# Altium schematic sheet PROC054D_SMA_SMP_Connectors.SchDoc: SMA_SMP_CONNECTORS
size 558 x 431 mm; Date: Not shown in title block; ApprovedBy: Not shown in title block; CheckedBy: Not shown in title block; Author: Not shown in title block; CompanyName: Not shown in title block; DrawnBy: a0271760; Engineer: Not shown in title block; Organization: Not shown in title block; Address1: Not shown in title block; Address2: Not shown in title block; Address3: Not shown in title block; Address4: Not shown in title block; DocumentNumber: 15; Revision: Use project pAWRameter SCH_Rev; SheetNumber: 15; SheetTotal: 19; PageSetup: Record=PageOptions¦CenterHorizontal=True¦CenterVertical=True¦PrintScale=1.00¦XCorrection=1.00¦YCorrection=1.00¦PrintKind=0¦BorderSize=5000000¦LeftOffset=0¦BottomOffset=0¦Orientation=2¦PaperLength=1000¦PaperWidth=1000¦Scale=100¦PaperSource=15¦PrintQuality=600¦MediaType=1¦DitherType=10¦PaperKind=Letter¦PrintScaleMode=1
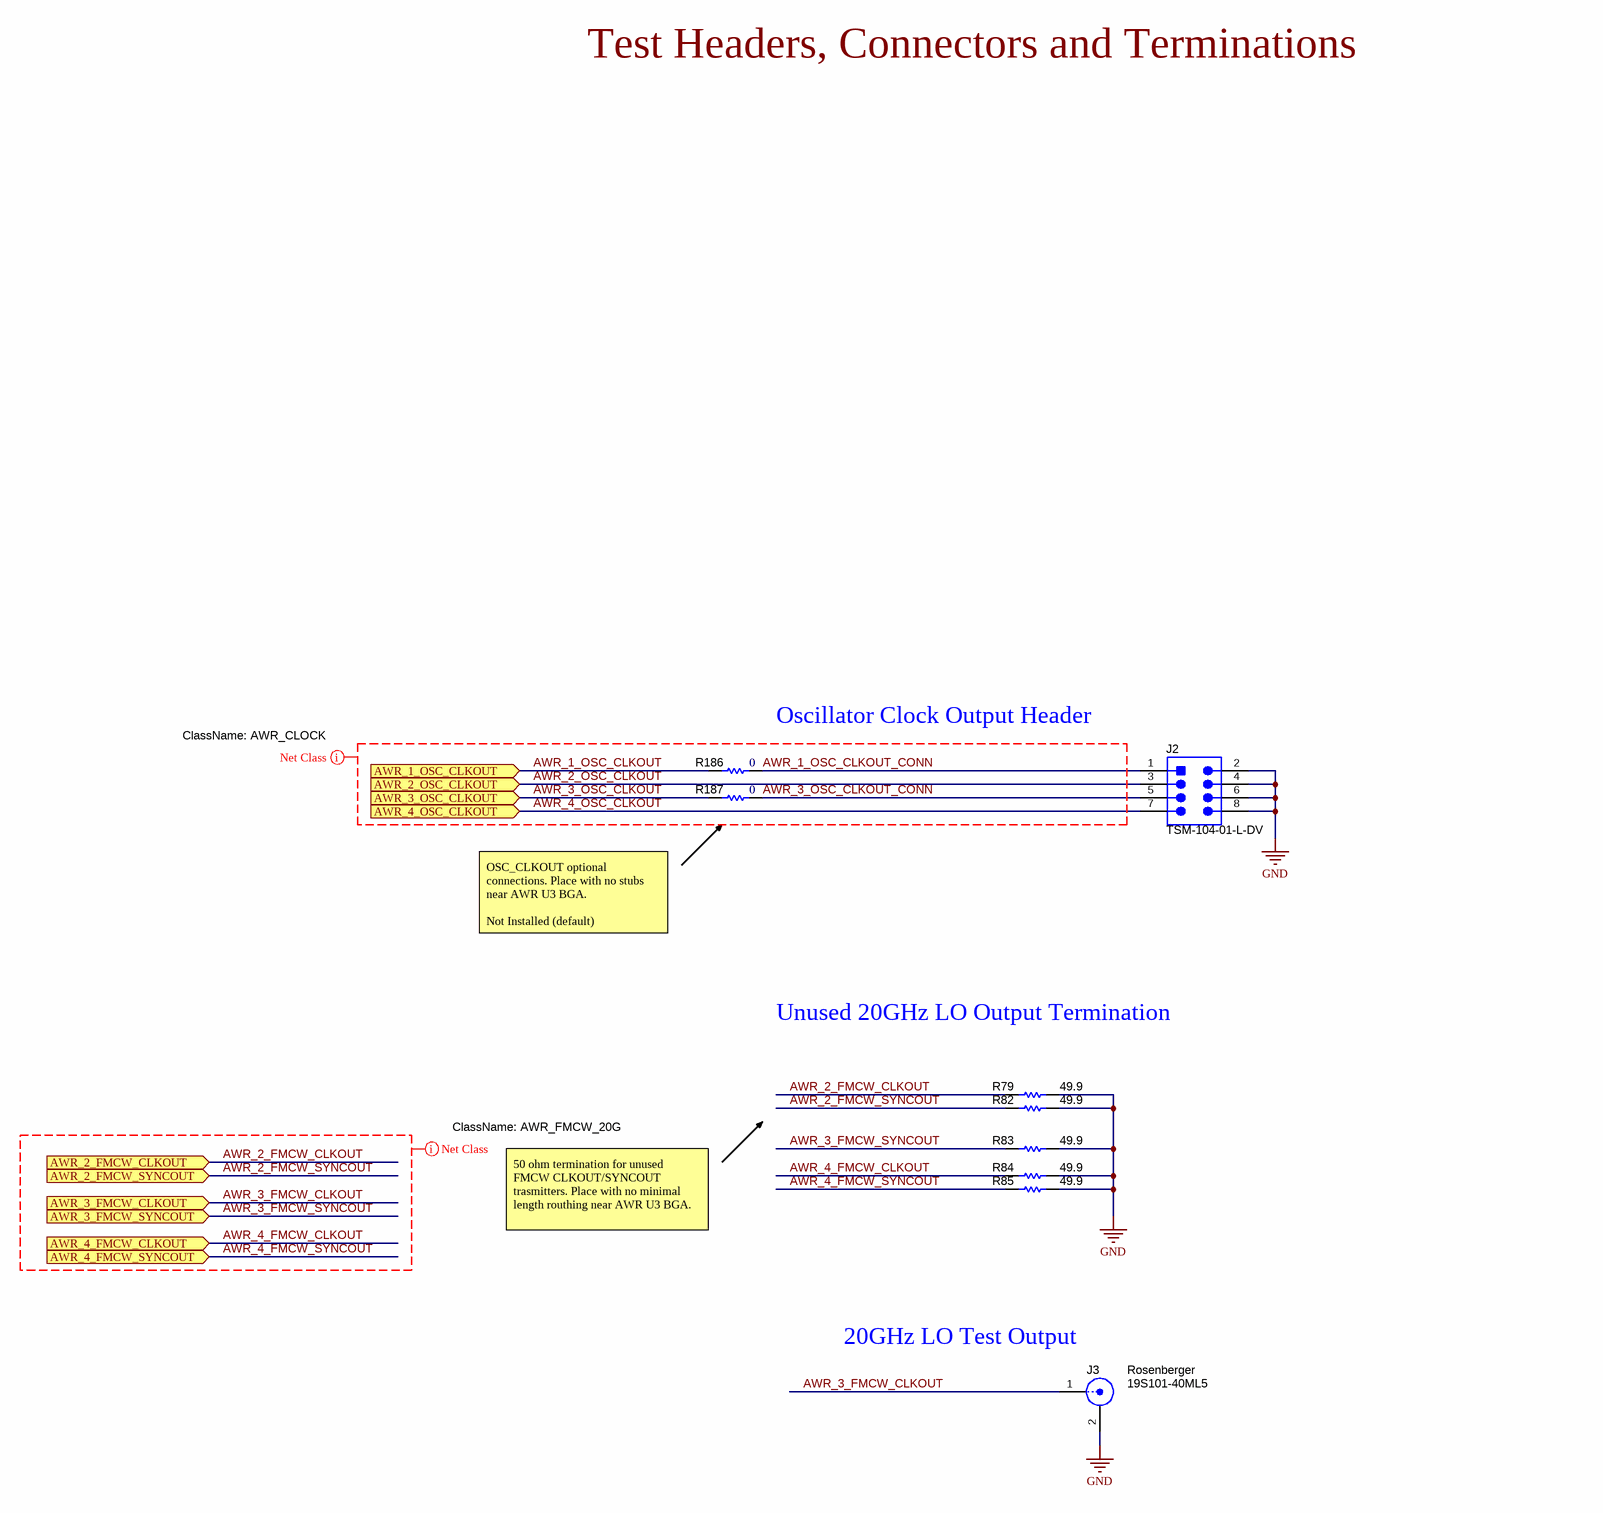
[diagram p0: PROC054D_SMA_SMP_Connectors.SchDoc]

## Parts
J2  TSM-104-01-L-DV  [Samtec_TSM-104-01-x-DV]
J3  19S101-40ML5  Manufacturer: Rosenberger  [19S101_40ML5]
R79  ValueDisplayed: 49.9  [0402]  (hidden comment: CRCW040249R9FKED)
R82  ValueDisplayed: 49.9  [0402]  (hidden comment: CRCW040249R9FKED)
R83  ValueDisplayed: 49.9  [0402]  (hidden comment: CRCW040249R9FKED)
R84  ValueDisplayed: 49.9  [0402]  (hidden comment: CRCW040249R9FKED)
R85  ValueDisplayed: 49.9  [0402]  (hidden comment: CRCW040249R9FKED)
R186  ValueDisplayed: 0  [0402S]  (hidden comment: ERJ-2GE0R00X)
R187  ValueDisplayed: 0  [0402S]  (hidden comment: ERJ-2GE0R00X)

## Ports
AWR_1_OSC_CLKOUT (in), AWR_2_FMCW_CLKOUT (in), AWR_2_FMCW_SYNCOUT (in), AWR_2_OSC_CLKOUT (in), AWR_3_FMCW_CLKOUT (in), AWR_3_FMCW_SYNCOUT (in), AWR_3_OSC_CLKOUT (in), AWR_4_FMCW_CLKOUT (in), AWR_4_FMCW_SYNCOUT (in), AWR_4_OSC_CLKOUT (in)

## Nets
GND: J2.2 J2.4 J2.6 J2.8 J3.2 R79.2 R82.2 R83.2 R84.2 R85.2
AWR_1_OSC_CLKOUT: R186.1 ; port AWR_1_OSC_CLKOUT
AWR_1_OSC_CLKOUT_CONN: J2.1 R186.2
AWR_2_FMCW_CLKOUT: R79.1 ; port AWR_2_FMCW_CLKOUT
AWR_2_FMCW_SYNCOUT: R82.1 ; port AWR_2_FMCW_SYNCOUT
AWR_2_OSC_CLKOUT: J2.3 ; port AWR_2_OSC_CLKOUT
AWR_3_FMCW_CLKOUT: J3.1 ; port AWR_3_FMCW_CLKOUT
AWR_3_FMCW_SYNCOUT: R83.1 ; port AWR_3_FMCW_SYNCOUT
AWR_3_OSC_CLKOUT: R187.1 ; port AWR_3_OSC_CLKOUT
AWR_3_OSC_CLKOUT_CONN: J2.5 R187.2
AWR_4_FMCW_CLKOUT: R84.1 ; port AWR_4_FMCW_CLKOUT
AWR_4_FMCW_SYNCOUT: R85.1 ; port AWR_4_FMCW_SYNCOUT
AWR_4_OSC_CLKOUT: J2.7 ; port AWR_4_OSC_CLKOUT

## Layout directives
net class AWR_FMCW_20G: AWR_2_FMCW_CLKOUT, AWR_2_FMCW_SYNCOUT, AWR_3_FMCW_CLKOUT, AWR_3_FMCW_SYNCOUT, AWR_4_FMCW_CLKOUT, AWR_4_FMCW_SYNCOUT
net class AWR_CLOCK: AWR_1_OSC_CLKOUT, AWR_1_OSC_CLKOUT_CONN, AWR_2_OSC_CLKOUT, AWR_3_OSC_CLKOUT, AWR_3_OSC_CLKOUT_CONN, AWR_4_OSC_CLKOUT

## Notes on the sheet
- Test Headers, Connectors and Terminations
- Oscillator Clock Output Header
- OSC_CLKOUT optional connections. Place with no stubs near AWR U3 BGA.
  Not Installed (default)
- Unused 20GHz LO Output Termination
- 50 ohm termination for unused FMCW CLKOUT/SYNCOUT trasmitters. Place with no minimal length routhing near AWR U3 BGA.
- (near J3) 20GHz LO Test Output

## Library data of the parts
J2 = CMP-0075593-2: Header, 2.54mm, 4x2, Gold, SMT; Manufacturer: Samtec; Pitch_mm: 2.54; Gender: Male; Cert_CSA: Y; Green_REACh: Passed; Current_A: 4.9A; Voltage_V: 475V; Shrouded: N; Green_Lifecycle: Active; Row_Count: 2
J3 = CMP-0055458-1: Connector, RF 50 Ohms, SMT; CT: FALSE
R79 R82-R85 = CMP-0026404-2: RES, 49.9, 1%, 0.063 W, AEC-Q200 Grade 0, 0402; Manufacturer: Vishay-Dale; Power_W: 63mW; TempCo: 100 ppm/C; Value_Code: 49R9; Value: 49.9; EIA_Code: E96; SizeX_mm: 1; SizeY_mm: 0.5; SizeZ_mm: 0.6; Value2: 0.063W; AEC Qualified: Y; VDC_V: 50V; AEC Category: Q200; AEC Grade: 0
R186 R187 = CMP-0026992-3: RES, 0, 5%, 0.1 W, AEC-Q200 Grade 0, 0402; Manufacturer: Panasonic; Power_W: 100mW; TempCo: 600 ppm/C; Value_Code: 0000; Value: 0; EIA_Code: E24; SizeX_mm: 1; SizeY_mm: 0.5; SizeZ_mm: 0.6; Value2: 0.1W; AEC Qualified: Y; VDC_V: 50V; AEC Category: Q200; SizeAreaWB_mm2: 3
